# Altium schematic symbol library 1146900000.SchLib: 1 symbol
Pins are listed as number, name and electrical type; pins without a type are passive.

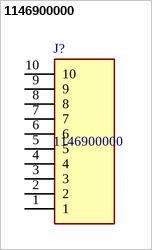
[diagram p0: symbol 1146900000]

## 1146900000
designator J?
PCB plug-in connector, male header, open side, THT solder connection, 5.08 mm, Number of poles: 10, 90, Solder pin length: 3.2 mm, tinned, orange, Box; Manufacturer_Name: Weidmuller; Geometry.Height: 8.4mm
footprint 1146900000
pins: 1, 2, 3, 4, 5, 6, 7, 8, 9, 10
